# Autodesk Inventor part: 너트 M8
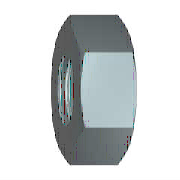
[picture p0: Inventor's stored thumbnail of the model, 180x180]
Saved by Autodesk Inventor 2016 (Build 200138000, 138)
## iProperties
IsCustomPart: 1
Created: 2012-02
Part Number: 너트 M8
Material: 강철, 연강
Description: 6각 너트
Document SubType Name: Modeling
Standard: KS B 1012
Designer: mduedu
Standards Organization: KS
Language: ko-KR
Size Designation: M8
Categories: <MemberInstance><Categories><Category DisplayName="조임쇠" InternalName="e4da775c-781d-43d5-af7c-5136215cf5a6" Mnemonic="FSTN"><Category DisplayName="너트" InternalN
Density: 1 g/cm^3
Appearance: 강철
Author: mduedu
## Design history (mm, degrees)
sketch "스케치1"
  geometry: L1 (-7.506, 0)-(-3.753, 6.5); L2 (-3.753, 6.5)-(3.753, 6.5); L3 (3.753, 6.5)-(7.506, 0); L4 (7.506, 0)-(3.753, -6.5); L5 (3.753, -6.5)-(-3.753, -6.5); L6 (-3.753, -6.5)-(-7.506, 0); 2 further points
  constraints: 12 end point, 1 coincident, 1 horizontal, 11 other
  dimensions: "d0" = 15.01111 distance of L3.end L1.start (= 1.1547 x SW)
extrude "본체" new body sketch "스케치1" distance "d1" = 5 (= KOH); taper "d2" = 0 deg
sketch "스케치2"
  geometry: L1 (0, 3.753)-(0, 7.506) reference; L2 (0, 7.506)-(5, 7.506) reference; L3 (5, 3.753)-(5, 7.506) reference; L4 (-1, 0)-(6, 0) reference; L5 (0.581, 7.506)-(0, 6.5); L6 (4.419, 7.506)-(5, 6.5)
  constraints: 4 end point, 4 point on line
  dimensions: "d3" = 30 deg angle of L1 L5 (= ANG1); "d4" = 30 deg angle of L3 L6 (= ANG2); "d5" = 13 diameter of L5.end L4 (= SW0); "d6" = 13 diameter of L6.end L4 (= SW01)
revolve "모따기1" sketch "스케치2" stored, may be unused: angle "d7" = 90 deg
sketch "스케치3"
  geometry: A1 r 6.5 centre (0, 0) between (-3.25, -5.629) and (3.25, -5.629) reference; 1 further point
  constraints: 1 coincident
hole "스레드" sketch "스케치3" at (0, 0) diameter "d25" = 6.647; stored, may be unused: countersink angle "d29" = 82 deg, drill point angle "d31" = 118 deg; dims "d26" = 6, "d27" = 4, "d28" = 2, "d30" = 8
workaxis "Work Axis1"
workplane "Work Plane1"
body "Solid1"
chamfer "모따기2" distance "d8" = 0.67658 (= -0.5 x GD1 + 0.5 x NND); stored, may be unused: angle "d9" = 30 deg, second distance "d40" = 0.67658 (= -0.5 x GD1 + 0.5 x NND)
chamfer "모따기3" distance "d10" = 0.67658 (= -0.5 x GD1 + 0.5 x NND); stored, may be unused: angle "d11" = 30 deg, second distance "d41" = 0.67658 (= -0.5 x GD1 + 0.5 x NND)
other parameters: "ANG1" = 30 deg [user parameter; used in 1 equation term], "ANG2" = 30 deg [user parameter; used in 1 equation term], "NND" = 8 [user parameter; used in 4 equation terms], "KOH" = 5 [user parameter; used in 1 equation term], "SW" = 13 [user parameter; used in 4 equation terms], "SW0" = 13 (= SW) [user parameter; used in 1 equation term], "SW01" = 13 (= SW) [user parameter; used in 1 equation term], "GD1" = 6.64684 (computed from THREADDIA, PTC, TOA) [user parameter; used in 4 equation terms], "d13" = 0, "d14" = 0, "d39" = 0, "d42" = 0, "GUL" = 0.67658 (= 0.541266 x PTC) [user parameter], "TPU" = 8 (computed from PTC) [user parameter], "THREADDIA" = 8 [user parameter; used in 1 equation term], "TOA" = 30 deg [user parameter; used in 1 equation term], "PTC" = 1.25 [user parameter; used in 4 equation terms], "E0" = 15.015 (= 1.155 x SW) [user parameter], "GAL" = 0.67658 (= 0.541266 x PTC) [user parameter]
